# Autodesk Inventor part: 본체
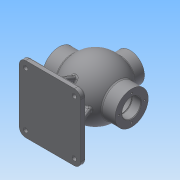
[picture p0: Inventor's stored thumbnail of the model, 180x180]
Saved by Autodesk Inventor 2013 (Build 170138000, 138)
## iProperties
Created: 2018-06
Part Number: 본체
Material: 일반
Document SubType Name: Modeling
Designer: Administrator
Density: 1 g/cm^3
Author: Administrator
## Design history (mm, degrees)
sketch "스케치1"
  geometry: L1 (-68, 0)-(68, 0); L2 (-42.988, 31)-(-68, 31); L3 (-68, 31)-(-68, 17.5); L4 (-68, 17.5)-(-39.278, 17.5); L5 (42.988, 31)-(68, 31); L6 (68, 31)-(68, 17.5); L7 (50.25, 18.5)-(52, 18.5); L8 (52, 18.5)-(52, 17.5); L9 (50.25, 17.5)-(50.25, 18.5); L10 (68, 17.5)-(52, 17.5); L11 (50.25, 17.5)-(39.278, 17.5); A1 r 53 centre (0, 0) between (42.988, 31) and (-42.988, 31); A2 r 43 centre (0, 0) between (39.278, 17.5) and (-39.278, 17.5); 2 further points
  constraints: 22 end point, 6 parallel, 4 point on circle, 3 coincident, 3 perpendicular, 2 centre point, 2 horizontal, 2 point on line, 1 collinear, 1 midpoint
  dimensions: "d0" = 136 distance of L1.start L1.end; "d2" = 106 diameter of A1; "d3" = 86 diameter of A2; "d4" = 35 diameter of L4 L1; "d5" = 62 diameter of L2 L1; "d7" = 62 diameter of L5 L1; "d8" = 37 diameter of L7 L1; "d9" = 16 distance between parallel lines of L8 L6; "d10" = 1.75 distance of L7.start L7.end; "d11" = 35 diameter of L10 L1
revolve "회전1" sketch "스케치1" stored, may be unused: angle "d12" = 90 deg
sketch "스케치2"
  geometry: L1 (-57.5, -75)-(57.5, -75); L2 (57.5, -75)-(57.5, -85); L3 (57.5, -85)-(-57.5, -85); L4 (-57.5, -85)-(-57.5, -75); 2 further points
  constraints: 8 end point, 2 parallel, 1 horizontal, 1 midpoint, 1 perpendicular, 1 vertical alignment
  dimensions: "d13" = 115 distance of L2.end L3.end; "d15" = 85 distance from line of point (0, 0) L3; "d16" = 10 distance of L1.end L2.end
extrude "돌출1" join sketch "스케치2" stored distance "d17" = 125; taper "d18" = 0 deg
sketch "스케치3"
  geometry: L1 (0, 125)-(115, 125) reference; L2 (61.5, 10)-(53.5, 10); L3 (53.5, 10)-(53.5, 115); L4 (53.5, 115)-(61.5, 115); L5 (61.5, 115)-(61.5, 10); L6 (61.5, 10)-(53.5, 115); L7 (53.5, 10)-(61.5, 115); 1 further point
  constraints: 12 end point, 2 midpoint, 2 parallel, 1 horizontal, 1 perpendicular
  dimensions: "d19" = 8 distance of L3.end L4.end; "d20" = 10 distance between parallel lines of L1 L4
extrude "돌출2" join sketch "스케치3" stored distance "d21" = 125; taper "d22" = 0 deg
feature "면 기울기1" dims angle "d23" = 22 deg
sketch "스케치4"
  geometry: L1 (47.5, -75)-(40.471, -57.604); L2 (57.5, -75)-(57.5, -85) reference; L3 (-57.5, -75)-(57.5, -75) reference; 1 further point
  constraints: 2 end point, 1 point on line
  dimensions: "d24" = 22 deg angle of L1 L2; "d25" = 10 distance from line of L2 L1.start
feature "리브1" sketch "스케치4" dims "d26" = 1, "d27" = 8, "d28" = 0, "d29" = 0, "d30" = 1, "d31" = 1
node "작업 평면1"
sketch "스케치6"
  geometry: C1 r 27 at (-57.5, -62.5); 1 further point
  constraints: 1 centre point, 1 coincident
  dimensions: "d38" = 54 diameter of C1
extrude "돌출4" join sketch "스케치6" stored distance "d39" = 125; taper "d40" = 0 deg
sketch "스케치7"
  geometry: C1 r 27 at (0, 0) reference; C2 r 13 at (0, 0)
  constraints: 1 centre point, 1 coincident
  dimensions: "d41" = 26 diameter of C2
extrude "돌출5" cut sketch "스케치7" stored distance "d42" = 125; taper "d43" = 0 deg
node "작업 평면2"
sketch "스케치8" dims "d13" = 115, "d15" = 85, "d16" = 10
  geometry: L1 (-27, 0)-(27, 0) reference; 2 further points
  constraints: 1 other
  dimensions: "d44" = 10 distance from line of point (0, -10) L1; "d45" = 27 horizontal distance of L1.start point (0, -10)
feature "엠보싱1" sketch "스케치8" dims "d0" = 136, "d2" = 106, "d3" = 86, "d4" = 35, "d5" = 62, "d7" = 62, "d8" = 37, "d9" = 16, "d10" = 1.75, "d11" = 35, "d13" = 115, "d15" = 85, "d16" = 10, "d46" = 0.5, "d47" = 0
fillet "모깎기1" dims "d48" = 12
fillet "모깎기2" dims "d49" = 3
fillet "모깎기3" dims "d50" = 3
fillet "모깎기4" dims "d51" = 3
sketch "스케치9"
  geometry: C1 r 6 at (0, -9); C2 r 6 at (91, -9); 1 further point
  constraints: 2 centre point, 1 horizontal alignment
  dimensions: "d52" = 12 diameter of C1; "d53" = 12 diameter of C2; "d54" = 45.5 horizontal distance of point (45.5, -59.5) C1.centre; "d55" = 50.5 vertical distance of point (45.5, -59.5) C1.centre; "d56" = 45.5 horizontal distance of point (45.5, -59.5) C2.centre
extrude "돌출6" cut sketch "스케치9" distance "d57" = 3; taper "d58" = 0 deg
sketch "스케치10"
  geometry: C1 r 4 at (0, -9); C2 r 4 at (91, -9); A1 r 9 centre (91, -9) between (100, -9) and (91, 0) reference; A2 r 9 centre (0, -9) between (0, 0) and (-9, -9) reference; 1 further point
  constraints: 2 centre point, 2 coincident
  dimensions: "d59" = 8 diameter of C1; "d60" = 8 diameter of C2
extrude "돌출7" cut sketch "스케치10" stored distance "d61" = 3; taper "d62" = 0 deg
fillet "모깎기5" dims "d63" = 3
sketch "스케치11"
  geometry: C1 r 13 at (0, 0) reference; 1 further point
  constraints: 1 vertical alignment
  dimensions: "d68" = 20 distance of C1.centre point (0, 20)
hole "구멍1" sketch "스케치11" at (0, 20) diameter "d69" = 3.242; stored, may be unused: countersink angle "d73" = 90 deg, drill point angle "d75" = 118 deg; dims "d70" = 9, "d71" = 4, "d72" = 2, "d74" = 11
sketch "스케치12"
  geometry: C1 r 17.5 at (0, 0) reference; 1 further point
  constraints: 1 vertical alignment
  dimensions: "d79" = 22.5 distance of C1.centre point (0, 22.5)
sketch "스케치13"
  geometry: C1 r 17.5 at (0, 0) reference; 1 further point
  constraints: 1 vertical alignment
  dimensions: "d90" = 24 distance of C1.centre point (0, 24)
hole "구멍3" sketch "스케치13" at (0, 24) diameter "d91" = 3.242; stored, may be unused: countersink angle "d95" = 90 deg, drill point angle "d97" = 118 deg; dims "d92" = 16, "d93" = 4, "d94" = 2, "d96" = 19
hole "구멍4" sketch "스케치12" diameter "d98" = 3.242; stored, may be unused: countersink angle "d102" = 90 deg, drill point angle "d104" = 118 deg; dims "d99" = 12, "d100" = 4, "d101" = 2, "d103" = 15
chamfer "모따기2" distance "d111" = 1; stored, may be unused: second distance "d112" = 2, angle "d113" = 45 deg
node "솔리드1"
mirror "대칭1"
mirror "대칭2"
mirror "대칭3"
pattern_circular "원형 패턴1" dims angle "d77" = 360 deg
pattern_circular "원형 패턴3" dims angle "d106" = 360 deg
pattern_circular "원형 패턴4" dims angle "d109" = 360 deg
other parameters: "d6" = 35
